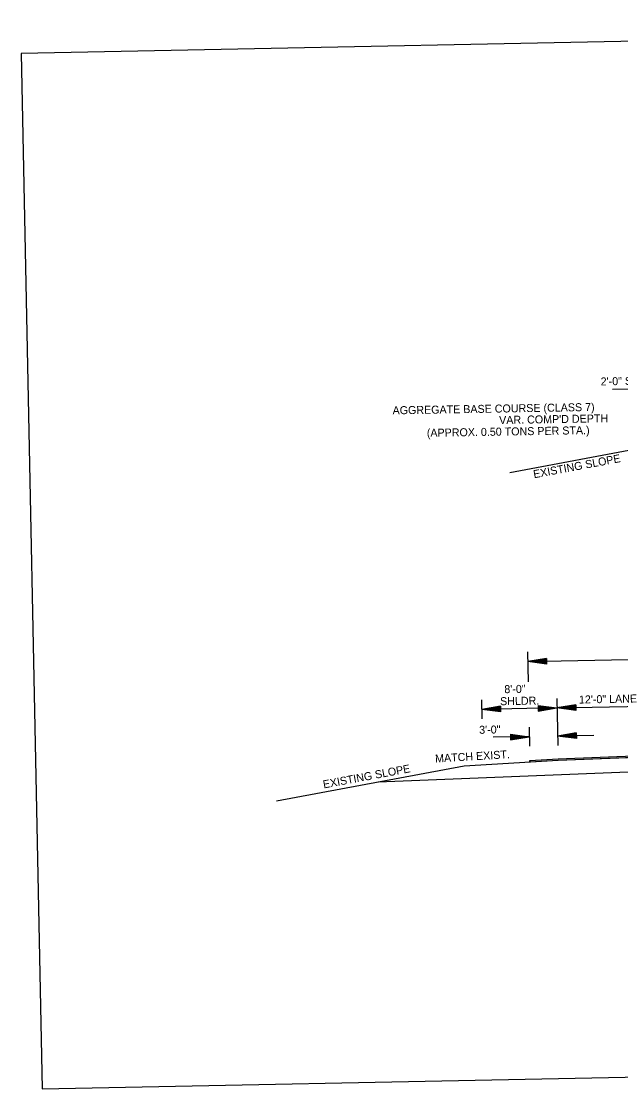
# Model space of a CAD drawing. Extents: x 174 to 869, y -36 to 177.
# Drawn here: x 696.6 to 760.3, y 64.1 to 177.4 of the extents above; entities that cross this region are included whole.
import ezdxf

# ---------------------------------------------------------------- set-up
doc = ezdxf.new("R2010")
doc.units = 0
for name, color, linetype in [('Default', 7, 'Continuous'), ('DSN_DRFT_Common-Annotations', 7, 'Continuous'), ('DSN_DRFT_Common-Line', 7, 'Continuous'), ('DSN_DRFT_Dimension', 7, 'Continuous')]:
    doc.layers.add(name, color=color, linetype=linetype)

msp = doc.modelspace()

# ---------------------------------------------------------------- linework, layer by layer
at = {"layer": 'DSN_DRFT_Common-Line'}
for p, q in [((768.48, 133.22), (748.55, 129.49)), ((750.43, 110.45), (750.49, 107.28)), ((753.53, 105.51), (753.63, 100.51)), ((745.53, 105.35), (745.57, 103.35)), ((750.59, 102.45), (750.63, 100.45)), ((783.14, 100.1), (753.66, 98.92)), ((753.66, 98.92), (743.67, 98.32)), ((750.66, 98.91), (750.67, 98.74)), ((743.67, 98.32), (723.74, 94.59)), ((783.18, 98.56), (734.56, 96.62))]:
    msp.add_line(p, q, dxfattribs=at)
for points in [[(696.61, 174.04), (698.81, 64.06), (868.78, 67.46), (866.58, 177.44)], [(812.65, 100.1), (783.14, 100.1), (753.66, 98.92), (750.67, 98.74), (750.66, 98.91), (753.66, 99.09), (783.14, 100.27), (812.65, 100.27), (815.65, 100.21), (815.65, 100.04)]]:
    msp.add_lwpolyline(points, close=True, dxfattribs=at)
at = {"layer": 'DSN_DRFT_Dimension'}
for p, q in [((759.44, 138.36), (768.37, 138.54)), ((750.45, 109.45), (815.44, 110.75)), ((752.45, 109.75), (750.45, 109.45)), ((752.45, 109.15), (750.45, 109.45)), ((752.45, 109.7), (750.79, 109.45)), ((752.45, 109.2), (750.79, 109.45)), ((752.45, 109.65), (751.13, 109.45)), ((752.45, 109.25), (751.13, 109.45)), ((752.45, 109.6), (751.46, 109.45)), ((752.45, 109.3), (751.46, 109.45)), ((752.45, 109.55), (751.8, 109.45)), ((752.45, 109.35), (751.8, 109.45)), ((752.45, 109.5), (752.14, 109.45)), ((752.45, 109.4), (752.14, 109.45)), ((752.45, 109.75), (752.45, 109.15)), ((747.55, 104.69), (745.55, 104.35)), ((753.55, 104.51), (745.55, 104.35)), ((747.56, 104.09), (745.55, 104.35)), ((747.55, 104.64), (745.89, 104.36)), ((747.56, 104.14), (745.89, 104.36)), ((747.55, 104.59), (746.23, 104.37)), ((747.56, 104.19), (746.23, 104.37)), ((747.55, 104.54), (746.56, 104.37)), ((747.56, 104.24), (746.56, 104.37)), ((747.55, 104.49), (746.9, 104.38)), ((747.55, 104.29), (746.9, 104.38)), ((747.55, 104.44), (747.24, 104.39)), ((747.55, 104.35), (747.24, 104.39)), ((747.55, 104.69), (747.56, 104.09)), ((751.55, 104.77), (753.55, 104.51)), ((751.55, 104.77), (751.56, 104.17)), ((751.55, 104.72), (753.22, 104.51)), ((751.55, 104.67), (752.87, 104.5)), ((751.55, 104.62), (752.54, 104.49)), ((751.55, 104.57), (752.2, 104.49)), ((751.55, 104.52), (751.87, 104.48)), ((751.55, 104.37), (752.2, 104.49)), ((751.55, 104.32), (752.54, 104.49)), ((751.55, 104.43), (751.87, 104.48)), ((751.56, 104.17), (753.55, 104.51)), ((751.56, 104.22), (753.22, 104.51)), ((751.56, 104.27), (752.87, 104.5)), ((755.54, 104.85), (753.55, 104.51)), ((753.55, 104.51), (765.55, 104.75)), ((755.56, 104.25), (753.55, 104.51)), ((755.55, 104.8), (753.88, 104.52)), ((755.56, 104.3), (753.88, 104.52)), ((755.55, 104.75), (754.23, 104.53)), ((755.55, 104.35), (754.23, 104.53)), ((755.55, 104.7), (754.56, 104.53)), ((755.55, 104.4), (754.56, 104.53)), ((755.55, 104.65), (754.9, 104.54)), ((755.55, 104.45), (754.9, 104.54)), ((755.55, 104.6), (755.23, 104.55)), ((755.55, 104.51), (755.23, 104.55)), ((755.54, 104.85), (755.56, 104.25)), ((750.61, 101.47), (746.75, 101.4)), ((748.61, 101.71), (750.61, 101.45)), ((748.61, 101.71), (748.62, 101.11)), ((748.61, 101.66), (750.28, 101.45)), ((748.61, 101.61), (749.93, 101.44)), ((748.61, 101.56), (749.6, 101.43)), ((748.61, 101.51), (749.26, 101.43)), ((748.61, 101.46), (748.93, 101.42)), ((748.61, 101.32), (749.26, 101.43)), ((748.61, 101.26), (749.6, 101.43)), ((748.61, 101.37), (748.93, 101.42)), ((748.62, 101.11), (750.61, 101.45)), ((748.62, 101.16), (750.28, 101.45)), ((748.62, 101.21), (749.93, 101.44)), ((755.6, 101.85), (753.61, 101.51)), ((757.47, 101.59), (753.61, 101.51)), ((755.62, 101.25), (753.61, 101.51)), ((755.61, 101.8), (753.94, 101.52)), ((755.62, 101.3), (753.94, 101.52)), ((755.61, 101.75), (754.29, 101.53)), ((755.61, 101.35), (754.29, 101.53)), ((755.61, 101.7), (754.62, 101.53)), ((755.61, 101.4), (754.62, 101.53)), ((755.61, 101.65), (754.96, 101.54)), ((755.61, 101.46), (754.96, 101.54)), ((755.61, 101.6), (755.29, 101.55)), ((755.61, 101.51), (755.29, 101.55)), ((755.6, 101.85), (755.62, 101.25))]:
    msp.add_line(p, q, dxfattribs=at)

# ---------------------------------------------------------------- texts
at = {"layer": 'Default'}
for s, p in [('AGGREGATE BASE COURSE (CLASS 7)', (736.08, 135.69)), ("VAR. COMP'D DEPTH", (747.41, 134.66)), ('(APPROX. 0.50 TONS PER STA.)', (739.72, 133.3))]:
    msp.add_text(s, height=0.85, rotation=0.9717, dxfattribs=at).set_placement(p)
at = {"layer": 'DSN_DRFT_Common-Annotations'}
for s, rotation, p in [('2\'-0" SHLDR.', 1.1458, (758.2, 138.76)), ('EXISTING SLOPE', 10.6078, (751.11, 128.9)), ('8\'-0"', 1.1458, (747.96, 106.07)), ('SHLDR.', 1.1458, (747.51, 104.79)), ('12\'-0" LANE', 1.1458, (755.89, 104.97)), (' 3\'-0"', 1.1458, (744.97, 101.75)), ('MATCH EXIST.', 3.4364, (740.62, 98.7)), ('EXISTING SLOPE', 10.6078, (728.76, 95.95))]:
    msp.add_text(s, height=0.85, rotation=rotation, dxfattribs=at).set_placement(p)

doc.saveas('drawing.dxf')
